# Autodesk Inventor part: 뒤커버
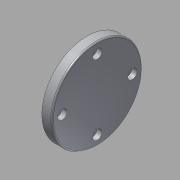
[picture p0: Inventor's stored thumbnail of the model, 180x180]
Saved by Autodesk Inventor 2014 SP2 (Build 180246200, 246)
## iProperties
Created: 2015-09
Part Number: 뒤커버
Material: 알루미늄 6061
Document SubType Name: Modeling
Designer: mduedu
Density: 2.71 g/cm^3
Mass: 54.0417 g
Surface Area: 84.9688 cm^2
Volume: 19.9416 cm^3
Appearance: 알루미늄 - 평지
Author: mduedu
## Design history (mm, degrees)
sketch "스케치1"
  geometry: L1 (-15.5, 47)-(-15.5, 78); L2 (-15.5, 78)-(-22.5, 78); L3 (-22.5, 78)-(-22.5, 67); L4 (-25.5, 67)-(-25.5, 47); L5 (-79.5, 39.5)-(-79.5, 54.5) reference; L6 (48.5, 54.5)-(48.5, 39.5) reference; L7 (-79.5, 47)-(48.5, 47); L8 (-22.5, 67)-(-25.5, 67); L9 (-25.5, 47)-(-15.5, 47); 1 further point
  constraints: 14 end point, 4 midpoint, 3 parallel, 1 collinear, 1 point on line, 1 vertical
  dimensions: "d6" = 62 diameter of L2 L7; "d7" = 7 distance of L1.end L2.end; "d8" = 40 diameter of L3.end L7; "d32" = 10 distance between parallel lines of L1 L4
revolve "회전1" sketch "스케치1" stored, may be unused: angle "d4" = 90 deg
sketch "스케치4"
  geometry: C1 r 31 at (0, 0) reference; 2 further points
  constraints: 1 coincident
hole "구멍3" sketch "스케치4" at (0, 0) diameter "d33" = 33; stored, may be unused: countersink angle "d37" = 90 deg, drill point angle "d39" = 0 deg; dims "d34" = 6, "d35" = 4, "d36" = 2, "d38" = 5
fillet "모깎기4" dims "d40" = 1
chamfer "모따기2" distance "d41" = 1; stored, may be unused: second distance "d42" = 2, angle "d43" = 45 deg
sketch "스케치5" dims "d44" = 48
  geometry: C1 r 31 at (0, 0) reference; 6 further points
  constraints: 2 vertical alignment, 1 coincident, 7 other
  dimensions: "d47" = 360 deg dimension on C1.centre point (0, -24) (derived)
sketch "스케치6"
  geometry: 4 further points
hole "구멍4" sketch "스케치6" at (24, 0), (0, 24), (-24, 0), (0, -24) diameter "d49" = 3.4; stored, may be unused: countersink angle "d53" = 90 deg, drill point angle "d55" = 0 deg; dims "d50" = 6, "d51" = 6.5, "d52" = 3.4, "d54" = 8
node "솔리드1"
node "참조1"
node "참조2"
